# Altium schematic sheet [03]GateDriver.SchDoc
size A4; SheetNumber: 3; SheetTotal: 5
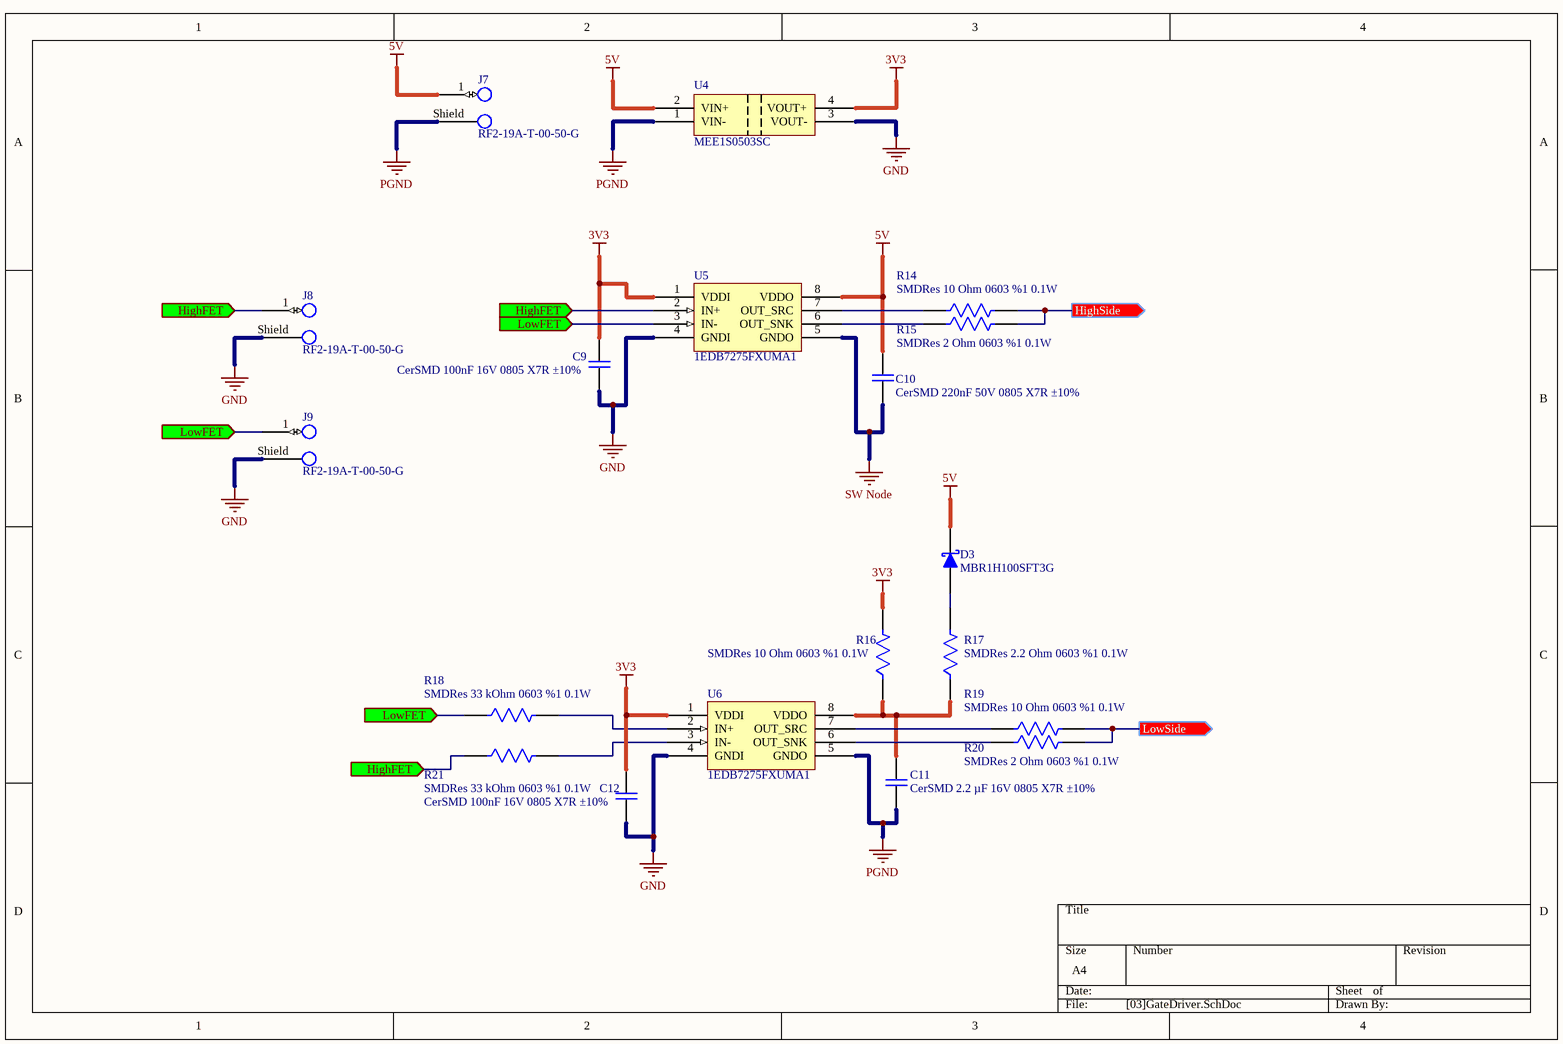
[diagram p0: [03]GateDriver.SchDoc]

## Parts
C9  CerSMD 100nF 16V 0805 X7R ±10%  [CAPC2012X09N]
C10  CerSMD 220nF 50V 0805 X7R ±10%  [CAPC2012X09N]
C11  CerSMD 2.2 µF 16V 0805 X7R ±10%  [CAPC2012X09N]
C12  CerSMD 100nF 16V 0805 X7R ±10%  [CAPC2012X09N]
D3  MBR1H100SFT3G  [SODFL360X95-2N]
J7  RF2-19A-T-00-50-G  [RF2-19A-T-00-50-G]
J8  RF2-19A-T-00-50-G  [RF2-19A-T-00-50-G]
J9  RF2-19A-T-00-50-G  [RF2-19A-T-00-50-G]
R14  SMDRes 10 Ohm 0603 %1 0.1W  [RESC1508X06N]
R15  SMDRes 2 Ohm 0603 %1 0.1W  [RESC1508X06N]
R16  SMDRes 10 Ohm 0603 %1 0.1W  [RESC1508X06N]
R17  SMDRes 2.2 Ohm 0603 %1 0.1W  [RESC1508X06N]
R18  SMDRes 33 kOhm 0603 %1 0.1W  [RESC1508X06N]
R19  SMDRes 10 Ohm 0603 %1 0.1W  [RESC1508X06N]
R20  SMDRes 2 Ohm 0603 %1 0.1W  [RESC1508X06N]
R21  SMDRes 33 kOhm 0603 %1 0.1W  [RESC1508X06N]
U4  MEE1S0503SC  [MEE1S0503SC-Footprint-1]
U5  1EDB7275FXUMA1  [SOIC127P600X175-8N]
U6  1EDB7275FXUMA1  [SOIC127P600X175-8N]

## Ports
HighFET (in, see [03]GateDriver[1B], [03]GateDriver[1C]), HighFET (in, see [03]GateDriver[1B], [03]GateDriver[2B]), HighFET (in, see [03]GateDriver[1C], [03]GateDriver[2B]), HighSide (out, see [05]BuckConverter[2B]), LowFET (in, see [03]GateDriver[1B], [03]GateDriver[1C]), LowFET (in, see [03]GateDriver[1B], [03]GateDriver[2B]), LowFET (in, see [03]GateDriver[1C], [03]GateDriver[2B]), LowSide (out, see [05]BuckConverter[2C])

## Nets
3V3: C9.1 C12.1 R16.2 U4.4(VOUT+) U5.1(VDDI) U6.1(VDDI)
5V: C10.1 D3.2(K) J7.1 U4.2(VIN+) U5.8(VDDO)
GND: C9.2 C12.2 J8.Shield J9.Shield U4.3(VOUT-) U5.4(GNDI) U6.4(GNDI)
PGND: C11.2 J7.Shield U4.1(VIN-) U6.5(GNDO)
SW Node: C10.2 U5.5(GNDO)
HighFET: J8.1 R21.1 U5.2(IN+) ; port HighFET
HighSide: R14.2 R15.2 ; port HighSide
LowFET: J9.1 R18.1 U5.3(IN-) ; port LowFET
LowSide: R19.2 R20.2 ; port LowSide
NetC11_1: C11.1 R16.1 R17.1 U6.8(VDDO)
NetD3_1: D3.1(A) R17.2
NetR14_1: R14.1 U5.7(OUT_SRC)
NetR15_1: R15.1 U5.6(OUT_SNK)
NetR18_2: R18.2 U6.2(IN+)
NetR19_1: R19.1 U6.7(OUT_SRC)
NetR20_1: R20.1 U6.6(OUT_SNK)
NetR21_2: R21.2 U6.3(IN-)

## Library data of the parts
C9 C12 = CMP-00013-1: Ceramic Capacitor SMD 100nF 10V 0805 X7R ±10%; Manufacturer Number: 885012207016; Manufacturer: Würth Elektronik
C10 = CMP-00016-1: Ceramic Capacitor SMD 220nF 50V 0805 X7R ±10%; Manufacturer: Murata Electronics; Manufacturer Number: GRM21BR71H224KA01L; Voltage: 10V
C11 = CMP-00014-1: Ceramic Capacitor SMD 2.2 µF 16V 0805 X7R ±10%; Manufacturer Number: C2012X7R1C225K125AB; Manufacturer: TDK Corporation
D3 = CMP-00020-2
J7-J9 = CMP-00025-2: Rf Sma Connector
R14 R16 R19 = CMP-00017-1: Res Thick Film 0603 10 Ohm Ohm 1% 0.1W(1/10W) ±100ppm/C Pad SMD T/R Automotive AEC-Q200; Manufacturer Number: RMCF0603FT10R0; Manufacturer: Stackpole Electronics Inc
R15 R20 = CMP-00019-1: Res Thick Film 0603 2 Ohm Ohm 1% 0.1W(1/10W) ±100ppm/C Pad SMD T/R Automotive AEC-Q200; Manufacturer: Stackpole Electronics Inc; Manufacturer Number: RMCF0603FT2R00
R17 = CMP-00015-1: Res Thick Film 0603 2.2 Ohm Ohm 1% 0.1W(1/10W) ±100ppm/C Pad SMD T/R Automotive AEC-Q200; Manufacturer Number: RMCF0603FT2R20; Manufacturer: Stackpole Electronics Inc
R18 R21 = CMP-00018-1: Res Thick Film 0603 33 kOhm Ohm 1% 0.1W(1/10W) ±100ppm/C Pad SMD T/R Automotive AEC-Q200; Manufacturer: Stackpole Electronics Inc; Manufacturer Number: RMCF0603FT33K0
U4 = CMP-00029-1: Murata Power - 5V to 3.3V Isolated DC-DC Converter 1W
U5 U6 = CMP-00012-1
